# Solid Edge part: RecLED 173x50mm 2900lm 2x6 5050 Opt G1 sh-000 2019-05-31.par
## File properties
Author: sylwester.cabaj
Template: iso metric part.par
Last saved by: sylwester.cabaj
Revision: 2
Application: Solid Edge
Gęstość: 0,000 kg/m^3
Dokładność: 0,990
Username: sylwester.cabaj
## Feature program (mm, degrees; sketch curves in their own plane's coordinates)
body "unnamed Body 1"
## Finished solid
Body 1: solid body, 508 faces, 1285 edges, 781 vertices.
  Faces by surface: plane 249, cylinder 125, spline 80, cone 26, torus 11, sphere 10, spun 7
  Edges by curve: line 724, curve on surface 282, circle 169, ellipse 66, spline 38, intersection 6
Bounding box of the edges (mm; curved faces can reach further): 49.500 x 4.950 x 172.200, from (-24.75, -3.45, -86.1) to (24.75, 1.5, 86.1).
Cylindrical faces by radius (mm): R0.2 x39, R0.2002 x2, R0.2169 x3, R0.25 x12, R0.3 x2, R0.3373 x3, R0.4 x8, R0.4006 x2, R0.4008 x2, R0.525 x2, R0.6 x12, R1 x7, R1.05 x12, R1.0894 x2, R1.1 x14, R1.75 x3
Conical faces (half-angle, radius in mm at the cone's reference point): 0.5 deg R0.5056 x4, 0.5 deg R1.0082 x4, 1 deg R0.5511 x2, 10 deg R0.2132 x2, 10 deg R0.4132 x2, 18.4844 deg R1.0657 x4, 27.363 deg R0.6214 x2, 45 deg R0.575 x2, 45 deg R0.625 x4
Toroidal faces (ring radius, tube radius in mm): R0.1 r0.2 x1, R0.8 r0.2 x4, R0.8522 r0.3 x2, R0.9002 r0.2 x1, R0.9018 r0.2 x1, R1.3 r0.2 x2
Spherical faces by radius (mm): R0.2 x8, R0.6 x2
Planar faces by outward normal: +x 25, +y 8, +z 21, -x 25, -y 44, -z 30, oblique 96
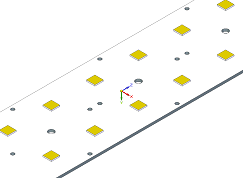
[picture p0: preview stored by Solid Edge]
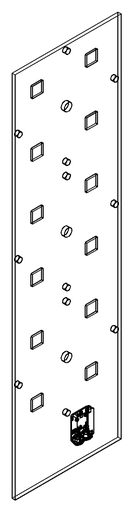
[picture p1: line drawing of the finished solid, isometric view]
